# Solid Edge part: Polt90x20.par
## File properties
Author: Türk
Template: Iso Part.par
Last saved by: Türk
Revision: 11
Application: Solid Edge
Accuracy: 0,990
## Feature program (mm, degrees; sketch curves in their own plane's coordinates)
thread "unnamed Thread 1"
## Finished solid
Body 1: solid body, 23 faces, 45 edges, 24 vertices.
  Faces by surface: plane 21, cylinder 2
  Edges by curve: line 42, circle 3
Bounding box of the edges (mm): 24.000 x 99.500 x 27.713, from (-12, -10, -13.8564) to (12, 89.5, 13.8564).
Cylindrical faces by radius (mm): R10 x2
Planar faces by outward normal: +x 1, +y 2, -x 1, -y 1, oblique 16
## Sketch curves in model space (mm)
circle centre (0, 0, 0) radius 13.8564
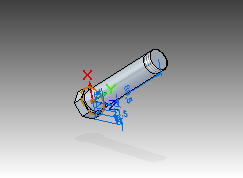
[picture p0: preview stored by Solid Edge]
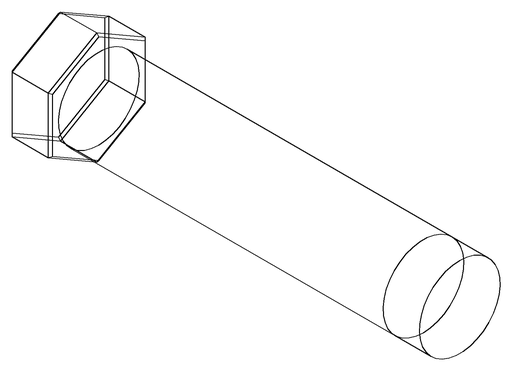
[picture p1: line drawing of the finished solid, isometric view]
